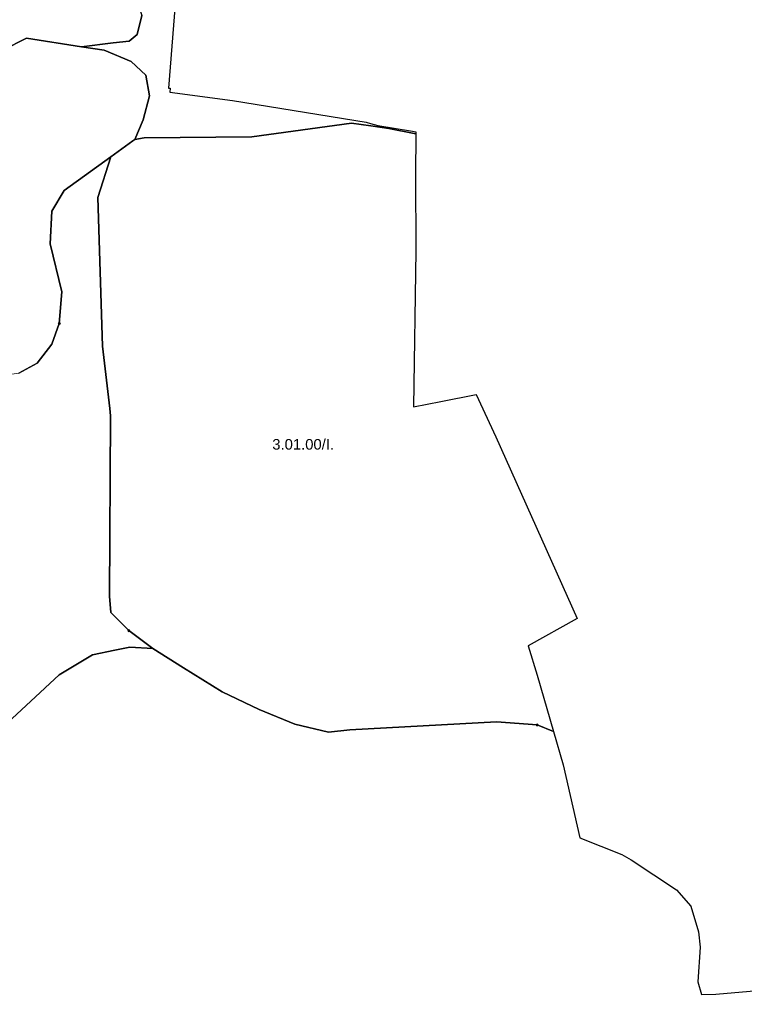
# Model space of a CAD drawing. Extents: x -650455 to -642254, y -1075222 to -1066610.
# Drawn here: x -645525 to -644838, y -1068549 to -1067624 of the extents above; entities that cross this region are included whole.
import ezdxf
from ezdxf.enums import TextEntityAlignment as Align

# ---------------------------------------------------------------- set-up
doc = ezdxf.new("R2010")
doc.units = 0
doc.header["$LTSCALE"] = 4
doc.header["$PDMODE"] = 32
doc.header["$PDSIZE"] = 2
for name, color, linetype, lineweight in [('1', 7, 'Continuous', 25), ('11', 7, 'Continuous', 13), ('12', 7, 'Continuous', 13), ('13', 7, 'Continuous', 13)]:
    doc.layers.add(name, color=color, linetype=linetype, lineweight=lineweight)
doc.layers.add('2', color=7, linetype='Continuous')

msp = doc.modelspace()

# ---------------------------------------------------------------- linework, layer by layer
at = {"layer": '1'}
msp.add_line((-645175, -1067727.5), (-645149.54, -1067732.723), dxfattribs=at)
for points in [[(-645375.661, -1066981.798), (-645383.686, -1067043.814), (-645384.878, -1067053.018), (-645390.401, -1067095.701), (-645418.542, -1067342.638), (-645409.605, -1067341.495), (-645361.617, -1067346.492), (-645371.183, -1067500.595), (-645371.73, -1067507.06), (-645372.231, -1067517.464), (-645374.197, -1067549.139), (-645376.168, -1067589.471), (-645383.93, -1067689.29), (-645382.349, -1067689.308), (-645382.611, -1067693.192), (-645323.149, -1067700.972), (-645196.557, -1067721.558), (-645192.4, -1067722.74), (-645185.42, -1067724.72), (-645152.82, -1067730.251), (-645149.527, -1067730.871), (-645149.54, -1067732.723)], [(-645416.812, -1067598), (-645409.312, -1067620.625), (-645413.813, -1067638.626), (-645421.375, -1067644.751), (-645436.375, -1067646.251), (-645466.563, -1067650.126)], [(-645466.563, -1067650.126), (-645518.5, -1067642.001), (-645541, -1067653.501), (-645542.25, -1067654.375), (-645576, -1067649.875), (-645619.125, -1067644.625), (-645689.063, -1067644.625), (-645710.625, -1067646.5), (-645790.875, -1067664.75), (-645796.062, -1067664.75), (-645802.687, -1067663.876), (-645790.813, -1067649.501), (-645777.5, -1067621.251)], [(-645149.54, -1067732.723), (-645175, -1067727.5), (-645192.189, -1067725.08), (-645192.187, -1067725.126), (-645210.5, -1067722.501), (-645305, -1067735.501), (-645407, -1067736.5), (-645416, -1067738.001), (-645408, -1067719.5), (-645402, -1067696.5), (-645405.5, -1067677.001), (-645419.5, -1067664), (-645445, -1067653.501), (-645466.563, -1067650.126), (-645436.375, -1067646.251), (-645421.375, -1067644.751), (-645413.813, -1067638.626), (-645409.312, -1067620.625)], [(-645541, -1067653.501), (-645518.5, -1067642.001), (-645466.563, -1067650.126)], [(-645466.563, -1067650.126), (-645445, -1067653.501), (-645419.5, -1067664), (-645405.5, -1067677.001), (-645402, -1067696.5), (-645408, -1067719.5), (-645416, -1067738.001), (-645417.864, -1067739.367), (-645417.875, -1067739.375), (-645438.5, -1067754.501), (-645483, -1067786.501), (-645494.5, -1067806), (-645496, -1067837), (-645485, -1067882.5), (-645487.5, -1067912.501), (-645494.5, -1067932), (-645508.5, -1067950.001), (-645526, -1067959.5)], [(-645149.54, -1067732.723), (-645149.832, -1067771.575), (-645149.522, -1067843.633), (-645151.695, -1067991.478), (-645125.846, -1067986.333), (-645092.396, -1067979.676), (-645073.768, -1068020.053), (-644996.462, -1068192.123), (-645043.032, -1068217.901), (-645034.339, -1068245.855), (-645018.928, -1068299.326), (-645034.5, -1068293.001), (-645073, -1068290.001), (-645212, -1068297.501), (-645232.313, -1068299.75), (-645232.441, -1068299.72), (-645264.313, -1068292.25), (-645297.937, -1068278.5), (-645333.063, -1068261.751), (-645369.687, -1068238.75), (-645398.687, -1068220.501), (-645421.625, -1068203.625), (-645438.375, -1068186.876), (-645438.625, -1068186.5), (-645440, -1068171.001), (-645439, -1068001.001), (-645439.063, -1068000), (-645439.5, -1067993.001), (-645446.5, -1067934), (-645451, -1067793), (-645438.5, -1067754.501), (-645417.875, -1067739.375), (-645417.864, -1067739.367), (-645416, -1067738.001), (-645407, -1067736.5), (-645305, -1067735.501), (-645210.5, -1067722.501), (-645192.187, -1067725.126), (-645192.189, -1067725.08), (-645175, -1067727.5)], [(-645494.5, -1067806), (-645483, -1067786.501), (-645438.5, -1067754.501), (-645451, -1067793), (-645446.5, -1067934), (-645439.5, -1067993.001), (-645439.063, -1068000), (-645439, -1068001.001), (-645440, -1068171.001), (-645438.625, -1068186.5), (-645438.375, -1068186.876), (-645421.625, -1068203.625), (-645398.687, -1068220.501)], [(-645526, -1067959.5), (-645508.5, -1067950.001), (-645494.5, -1067932), (-645487.5, -1067912.501), (-645485, -1067882.5), (-645496, -1067837), (-645494.5, -1067806)], [(-645546, -1068299.5), (-645487.5, -1068245.501), (-645456, -1068226.5), (-645434.909, -1068222.163), (-645420.75, -1068219.25), (-645398.687, -1068220.501), (-645369.687, -1068238.75), (-645333.063, -1068261.751), (-645297.937, -1068278.5), (-645264.313, -1068292.25), (-645232.441, -1068299.72)], [(-645398.687, -1068220.501), (-645420.75, -1068219.25), (-645434.909, -1068222.163), (-645456, -1068226.5), (-645487.5, -1068245.501), (-645546, -1068299.5)], [(-645232.441, -1068299.72), (-645232.313, -1068299.75), (-645212, -1068297.501), (-645073, -1068290.001), (-645034.5, -1068293.001), (-645018.928, -1068299.326), (-645009.812, -1068330.959), (-644993.919, -1068400.05), (-644954.179, -1068415.889), (-644945.486, -1068420.86), (-644902.534, -1068449.199), (-644888.874, -1068464.728), (-644881.423, -1068489.266), (-644879.87, -1068503.552), (-644882.043, -1068536.476), (-644878.622, -1068548.552), (-644865.029, -1068548.219), (-644785.549, -1068541.387)]]:
    msp.add_lwpolyline(points, dxfattribs=at)
at = {"layer": '11'}
msp.add_line((-645297.937, -1068278.5), (-645264.313, -1068292.25), dxfattribs=at)
for points in [[(-645409.312, -1067620.625), (-645413.813, -1067638.626), (-645421.375, -1067644.751), (-645436.375, -1067646.251), (-645466.563, -1067650.126), (-645445, -1067653.501), (-645419.5, -1067664), (-645405.5, -1067677.001), (-645402, -1067696.5), (-645408, -1067719.5), (-645416, -1067738.001), (-645407, -1067736.5), (-645305, -1067735.501), (-645210.5, -1067722.501), (-645192.187, -1067725.126), (-645192.189, -1067725.08), (-645175, -1067727.5), (-645149.54, -1067732.723), (-645149.527, -1067730.871), (-645152.82, -1067730.251), (-645185.42, -1067724.72), (-645192.4, -1067722.74), (-645196.557, -1067721.558), (-645323.149, -1067700.972), (-645382.611, -1067693.192), (-645382.349, -1067689.308), (-645383.93, -1067689.29), (-645376.168, -1067589.471)], [(-645264.313, -1068292.25), (-645232.441, -1068299.72), (-645232.313, -1068299.75), (-645212, -1068297.501), (-645073, -1068290.001), (-645034.5, -1068293.001), (-645018.928, -1068299.326), (-645034.339, -1068245.855), (-645043.032, -1068217.901), (-644996.462, -1068192.123), (-645073.768, -1068020.053), (-645092.396, -1067979.676), (-645125.846, -1067986.333), (-645151.695, -1067991.478), (-645149.522, -1067843.633), (-645149.832, -1067771.575), (-645149.54, -1067732.723), (-645175, -1067727.5), (-645192.189, -1067725.08), (-645192.187, -1067725.126), (-645210.5, -1067722.501), (-645305, -1067735.501), (-645407, -1067736.5), (-645416, -1067738.001), (-645417.864, -1067739.367), (-645417.875, -1067739.375), (-645438.5, -1067754.501), (-645451, -1067793), (-645446.5, -1067934), (-645439.5, -1067993.001), (-645439.063, -1068000), (-645439, -1068001.001), (-645440, -1068171.001), (-645438.625, -1068186.5), (-645438.375, -1068186.876), (-645421.625, -1068203.625), (-645398.687, -1068220.501), (-645369.687, -1068238.75), (-645333.063, -1068261.751), (-645297.937, -1068278.5)], [(-645421.625, -1068203.625), (-645438.375, -1068186.876), (-645438.625, -1068186.5), (-645440, -1068171.001), (-645439, -1068001.001), (-645439.063, -1068000), (-645439.5, -1067993.001), (-645446.5, -1067934), (-645451, -1067793), (-645438.5, -1067754.501), (-645483, -1067786.501), (-645494.5, -1067806), (-645496, -1067837), (-645485, -1067882.5), (-645487.5, -1067912.501)], [(-645487.5, -1067912.501), (-645494.5, -1067932), (-645508.5, -1067950.001), (-645526, -1067959.5), (-645546.5, -1067962.5)], [(-645791.5, -1068490.5), (-645783, -1068502.5), (-645771, -1068497), (-645757, -1068486), (-645754.063, -1068483.625), (-645712.527, -1068450.515), (-645712.513, -1068450.504), (-645692.438, -1068434.501), (-645613.5, -1068371.5), (-645546, -1068299.5), (-645487.5, -1068245.501), (-645456, -1068226.5), (-645434.909, -1068222.163), (-645420.75, -1068219.25), (-645398.687, -1068220.501), (-645421.625, -1068203.625)], [(-645034.5, -1068293.001), (-645073, -1068290.001), (-645212, -1068297.501), (-645232.313, -1068299.75), (-645232.441, -1068299.72), (-645264.313, -1068292.25), (-645297.937, -1068278.5), (-645333.063, -1068261.751), (-645369.687, -1068238.75), (-645398.687, -1068220.501), (-645420.75, -1068219.25), (-645434.909, -1068222.163), (-645456, -1068226.5), (-645487.5, -1068245.501), (-645546, -1068299.5)], [(-644785.549, -1068541.387), (-644865.029, -1068548.219), (-644878.622, -1068548.552), (-644882.043, -1068536.476), (-644879.87, -1068503.552), (-644881.423, -1068489.266), (-644888.874, -1068464.728), (-644902.534, -1068449.199), (-644945.486, -1068420.86), (-644954.179, -1068415.889), (-644993.919, -1068400.05), (-645009.812, -1068330.959), (-645018.928, -1068299.326), (-645034.5, -1068293.001)]]:
    msp.add_lwpolyline(points, dxfattribs=at)
for p in [(-645487.5, -1067912.501), (-645421.625, -1068203.625), (-645034.5, -1068293.001)]:
    msp.add_point(p, dxfattribs=at)
at = {"layer": '12'}
msp.add_lwpolyline([(-645710.625, -1067646.5), (-645689.063, -1067644.625), (-645619.125, -1067644.625), (-645576, -1067649.875), (-645542.25, -1067654.375), (-645541, -1067653.501), (-645518.5, -1067642.001), (-645466.563, -1067650.126), (-645436.375, -1067646.251), (-645421.375, -1067644.751), (-645413.813, -1067638.626), (-645409.312, -1067620.625)], dxfattribs=at)
at = {"layer": '13'}
msp.add_lwpolyline([(-645526, -1067959.5), (-645508.5, -1067950.001), (-645494.5, -1067932), (-645487.5, -1067912.501), (-645485, -1067882.5), (-645496, -1067837), (-645494.5, -1067806), (-645483, -1067786.501), (-645438.5, -1067754.501), (-645417.875, -1067739.375), (-645417.864, -1067739.368), (-645416, -1067738.001), (-645408, -1067719.5), (-645402, -1067696.5), (-645405.5, -1067677.001), (-645419.5, -1067664), (-645445, -1067653.501), (-645466.563, -1067650.126), (-645518.5, -1067642.001), (-645541, -1067653.501)], dxfattribs=at)

# ---------------------------------------------------------------- texts
at = {"layer": '2', "width": 1.05}
msp.add_text('3.01.00/I.', height=10, dxfattribs=at).set_placement((-645256.326, -1068031.995), align=Align.CENTER)

doc.saveas('drawing.dxf')
